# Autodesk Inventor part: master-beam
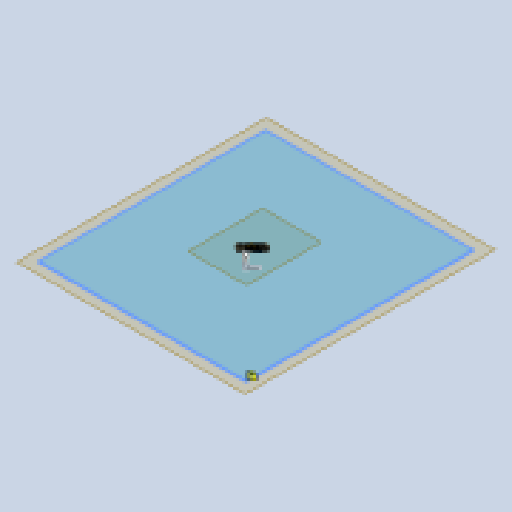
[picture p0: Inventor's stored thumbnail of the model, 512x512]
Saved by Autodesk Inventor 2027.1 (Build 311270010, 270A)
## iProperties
Created: 2026-07
Part Number: master-beam
Material: Generic
Document SubType Name: Modeling
Designer: dunge
Density: 1 g/cm^3
Appearance: Default
Author: dunge
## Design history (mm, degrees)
sketch "master sketch"
  geometry: L1 (0, 0)-(0, 228.6); L2 (0, 228.6)-(-114.3, 228.6); L3 (-114.3, 228.6)-(-114.3, 69.85); L4 (-292.1, 69.85)-(-292.1, 171.45); L5 (-342.9, 69.85)-(-342.9, -35.56); L6 (-342.9, -35.56)-(-241.3, -35.56); L7 (-342.9, -35.56)-(-342.9, 120.808); L8 (-114.3, 69.85)-(-114.3, -6.35); L9 (-342.9, -35.56)-(-342.9, -187.96); 31 further points; 1 other entity
  constraints: 24 point on line, 18 end point, 5 vertical, 3 perpendicular, 1 coincident, 1 midpoint, 10 other
  dimensions: "d0" = 228.6 distance of L1.start L1.end; "d1" = 304.8 distance of L3.end point (-419.1, 69.85); "d2" = 101.6 distance of L4.start L4.end; "d4" = 114.3 distance of L1.end L2.end; "d5" = 76.2 distance of L3.end L8.end; "d6" = 177.8 distance between parallel lines of L3 L4; "d9" = 19.05 distance of point (-190.5, 69.85) point (-171.45, 69.85); "d10" = 19.05 distance of point (-254, 69.85) point (-234.95, 69.85); "d11" = 44.45 distance of point (-234.95, 69.85) point (-190.5, 69.85); "d12" = 57.15 distance from line of L8 point (-171.45, 69.85); "d13" = 127 distance of L1.start point (0, 127); "d14" = 38.1 distance of point (-114.3, 190.5) point (-114.3, 152.4); "d15" = 38.1 distance from line of L2 point (-114.3, 190.5); "d16" = 17.78 distance of point (-342.9, 20.32) point (-342.9, 2.54); "d17" = 17.78 distance of point (-342.9, 20.32) point (-342.9, 38.1); "d18" = 16.51 distance of point (-342.9, -152.4) point (-342.9, -168.91); "d20" = 16.51 distance of point (-342.9, -73.66) point (-342.9, -90.17); "d26" = 152.4 distance of L5.end L9.end; "d27" = 31.75 distance of L5.start point (-342.9, 38.1); "d29" = 35.56 distance of point (-269.24, -35.56) point (-304.8, -35.56); "d40" = 38.1 distance from line of point (-342.9, -73.66) L6; "d42" = 21.59 distance of point (-342.9, -111.76) point (-342.9, -90.17); "d43" = 15.24 distance of point (-342.9, -137.16) point (-342.9, -152.4); "d44" = 25.4 distance of point (-342.9, -137.16) point (-342.9, -111.76); "d45" = 25.4 distance of point (0, 171.45) point (0, 146.05); "d46" = 19.05 distance of point (0, 146.05) point (0, 127); "d47" = 31.75 distance of L3.end point (-114.3, 38.1); "d48" = 31.75 distance of L3.end point (-114.3, 101.6); "d49" = 50.8 distance of point (-114.3, 101.6) point (-114.3, 152.4); "d51" = 31.75 distance of L3.end point (-146.05, 69.85); "d52" = 20.32 distance of point (-292.1, 101.6) point (-292.1, 121.92); "d53" = 20.32 distance of point (-292.1, 142.24) point (-292.1, 121.92); "d54" = 31.75 distance of L4.start point (-292.1, 101.6); "d87" = 101.6 distance of L5.end L6.end; "d88" = 17.78 distance of point (-304.8, -35.56) point (-287.02, -35.56); "d89" = 38.1 distance from line of L7 point (-304.8, -35.56); "d90" = 38.1 distance of point (-342.9, 2.54) L5.end; "d94" = 50.8 distance between parallel lines of L4 L7
workpoint "Work Point1"
workpoint "Work Point2"
workpoint "Work Point3"
workpoint "Work Point4"
workpoint "Work Point5"
workpoint "Work Point6"
workpoint "Work Point7"
workpoint "Work Point8"
workpoint "Work Point9"
workpoint "Work Point10"
workpoint "Work Point11"
workpoint "Work Point12"
workpoint "Work Point13"
workpoint "Work Point14"
workpoint "Work Point15"
workpoint "Work Point16"
workpoint "Work Point17"
workpoint "Work Point18"
workpoint "Work Point19"
workpoint "Work Point20"
workpoint "Work Point21"
workpoint "Work Point22"
workpoint "Work Point23"
workpoint "Work Point24"
workpoint "Work Point25"
sketch "Sketch2"
  geometry: L1 (-114.3, 69.85)-(-419.1, 69.85) reference; L2 (-114.3, 59.69)-(-419.1, 59.69); L3 (-419.1, 59.69)-(-419.1, 69.85); L4 (-114.3, 59.69)-(-114.3, 69.85); 1 further point
  constraints: 6 end point, 2 parallel, 1 vertical
  dimensions: "THICK_BEAM_RADIUS" = 10.16 distance between parallel lines of L1 L2
revolve "Revolution1" sketch "Sketch2" stored, may be unused: angle "d23" = 90 deg
workpoint "Work Point26"
sketch "Sketch3"
  geometry: L1 (-292.1, 69.85)-(-292.1, 171.45) reference; L2 (-302.26, 59.831)-(-302.26, 143.51); L3 (-302.26, 59.831)-(-292.1, 59.831); L4 (-302.26, 143.51)-(-297.307, 171.858); L5 (-297.307, 171.858)-(-297.307, 176.674); L6 (-297.307, 176.674)-(-292.1, 176.674); L7 (-292.1, 176.674)-(-292.1, 171.45); L8 (-292.1, 59.831)-(-292.1, 69.85); 2 further points
  constraints: 14 end point, 2 perpendicular, 2 vertical, 1 collinear, 1 parallel
  dimensions: "d24" = 10.16 distance between parallel lines of L1 L2 (derived); "d56" = 1.27 vertical distance of L2.end point (-292.1, 142.24); "d57" = 5.207 distance between parallel lines of L7 L5; "d58" = 5.22357 distance of L6.end L1.end; "d59" = 4.81531 distance of L4.end L5.end
revolve "LED Beam" sketch "Sketch3" stored, may be unused: angle "d25" = 360 deg
workpoint "Work Point27"
workpoint "Work Point28"
workpoint "Work Point29"
workpoint "Work Point30"
workpoint "Work Point31"
workpoint "Work Point32"
workpoint "Work Point33"
workpoint "Work Point34"
workpoint "Work Point35"
workpoint "Work Point36"
sketch "Sketch4"
  geometry: L1 (-114.3, 228.6)-(-114.3, 69.85) reference; L2 (-104.14, -6.35)-(-104.14, 152.4); L3 (-111.76, 152.4)-(-116.84, 152.4); L4 (-114.3, -6.35)-(-104.14, -6.35); L5 (-111.76, 228.6)-(-114.3, 228.6); L6 (-116.84, 190.5)-(-111.76, 190.5); L7 (-111.76, 190.5)-(-111.76, 228.6); L8 (-104.14, 152.4)-(-114.046, 183.356); L9 (-114.046, 183.356)-(-111.76, 190.5); L10 (-114.3, 69.85)-(-114.3, -6.35) reference; L11 (-113.965, 183.61)-(-114.3, 183.61); L12 (-113.965, 183.102)-(-114.3, 183.102); 4 further points
  constraints: 21 end point, 4 perpendicular, 4 point on line, 2 midpoint, 2 parallel, 2 vertical, 1 horizontal, 1 horizontal alignment, 1 vertical alignment
  dimensions: "d33" = 0.254 distance from line of L1 L8.end; "d60" = 0.254 distance from line of L8.end L11; "d61" = 0.254 distance from line of L8.end L12; "THIN_BEAM_RADIUS" = 2.54 distance between parallel lines of L1 L7; "d63" = 10.16 distance between parallel lines of L1 L2 (derived)
revolve "Revolution3" sketch "Sketch4" stored, may be unused: angle "d34" = 360 deg
workplane "Work Plane1"
sketch "Sketch6"
  geometry: L1 (11597.715, 14740.167)-(-14176.276, 14740.167); L2 (-14176.276, 14740.167)-(-14176.276, -13449.358); L3 (-14176.276, -13449.358)-(11597.715, -13449.358); L4 (11597.715, -13449.358)-(11597.715, 14740.167); 1 further point
  constraints: 8 end point, 2 parallel, 1 horizontal, 1 perpendicular
extrude "Extrusion2" new body sketch "Sketch6" distance "d38" = 25.4; taper "d39" = 0 deg
workpoint "Work Point37"
workpoint "Work Point38"
workpoint "Work Point39"
workpoint "Work Point40"
workpoint "Work Point41"
workpoint "Work Point42"
workpoint "Work Point43"
workpoint "Work Point44"
workplane "Work Plane2"
sketch "Sketch7"
  geometry: L1 (0, 228.6)-(-114.3, 228.6) reference; L2 (0, 0)-(0, 228.6) reference; L3 (0, 145.605)-(0, 146.494) reference; 3 further points
  constraints: 2 end point, 1 vertical, 2 other
workpoint "Work Point45"
workpoint "Work Point46"
workpoint "Work Point47"
workpoint "Work Point48"
workpoint "Work Point49"
sketch "Sketch8"
  geometry: L1 (-116.84, 228.6)-(-111.76, 228.6) reference; 2 further points
  constraints: 1 horizontal alignment, 1 midpoint, 2 other
extrude "Extrusion3" join sketch "Sketch8" distance "d64" = 19.05; taper "d65" = 0 deg
workplane "Work Plane3"
sketch "Sketch9"
  geometry: L1 (2.54, 0)-(-2.54, 0) reference; C1 r 12.7 at (0, 0); 1 further point
  constraints: 1 centre point, 1 midpoint
  dimensions: "d66" = 25.4 diameter of C1
extrude "Extrusion4" cut sketch "Sketch9" distance "d67" = 19.05; taper "d68" = 0 deg
sketch "Sketch10"
  geometry: L1 (0, 228.6)-(-114.3, 228.6) reference; L2 (0, 0)-(0, 228.6) reference; L3 (-114.3, 228.6)-(0, 228.6); L4 (0, 228.6)-(0, 231.14); L5 (0, 231.14)-(-114.3, 231.14); L6 (-114.3, 231.14)-(-114.3, 228.6); L7 (0, 228.6)-(2.54, 228.6); L8 (2.54, 228.6)-(2.54, 0); L9 (2.54, 0)-(0, 0); L10 (0, 0)-(0, 228.6); 4 further points
  constraints: 16 end point, 4 parallel, 2 horizontal, 2 perpendicular
  dimensions: "d69" = 2.54 distance of L8.end L9.end (derived); "d70" = 2.54 distance of L3.end L4.end (derived)
revolve "Revolution4" stored, may be unused: angle "d71" = 90 deg
revolve "Revolution5" stored, may be unused: angle "d72" = 360 deg
workplane "Work Plane4"
sketch "Sketch11"
  geometry: C1 r 10.368 at (-0.227, -0.06); 1 further point
  constraints: 1 centre point
extrude "Extrusion5" cut sketch "Sketch11" distance "d73" = 19.05; taper "d74" = 0 deg
workplane "Work Plane5"
sketch "Sketch12"
  geometry: L1 (-2.54, 0)-(2.54, 0) reference; C1 r 24.504 at (-0.617, 0); 1 further point
  constraints: 1 centre point, 1 point on line
extrude "Extrusion6" cut sketch "Sketch12" distance "d75" = 19.05; taper "d76" = 0 deg
sketch "Sketch13"
  geometry: L1 (-342.9, 54.915)-(-342.9, 84.785) reference; L2 (-357.835, 69.85)-(-327.965, 69.85) reference; L3 (-342.9, 20.411)-(-342.9, -33.65) reference; L4 (-241.554, -25.281)-(-241.554, -46.853) reference; L5 (-352.74, -183.96)-(-333.06, -183.96) reference; L6 (-342.9, -280.735)-(-342.9, -133.286) reference; L7 (-342.9, 69.85)-(-332.74, 59.69); L8 (-332.74, 59.69)-(-332.74, -10.16); L9 (-332.74, -10.16)-(-342.9, -35.56); L10 (-342.9, -35.56)-(-317.5, -45.72); L11 (-342.9, -35.56)-(-353.06, -60.96); L12 (-342.9, 54.915)-(-342.9, 2.54); L13 (-353.06, -60.96)-(-353.06, -168.91); L14 (-353.06, -168.91)-(-346.71, -183.96); L15 (-342.9, -133.286)-(-342.9, -33.65); L16 (-317.5, -45.72)-(-269.24, -45.72); L17 (-269.24, -45.72)-(-239.875, -38.733); L18 (-239.875, -38.733)-(-239.875, -35.56); L19 (-241.241, -35.56)-(-342.9, -35.56); L20 (-241.241, -35.56)-(-239.875, -35.56); L21 (-241.554, -35.56)-(-241.554, -39.132); L22 (-342.9, -35.56)-(-353.06, -60.96); L23 (-353.06, -168.91)-(-346.71, -183.96); L24 (-342.9, -183.96)-(-342.9, -35.56); 9 further points
  constraints: 44 end point, 8 vertical, 6 point on line, 3 collinear, 3 horizontal, 3 perpendicular, 2 midpoint, 1 horizontal alignment, 1 vertical alignment, 8 other
  dimensions: "d78" = 45 deg angle of L1 L7; "d79" = 10.16 distance between parallel lines of L1 L8 (derived); "d80" = 10.16 distance between parallel lines of L15 L13 (derived); "d82" = 3.17252 distance of L17.end L18.end; "d83" = 1.67902 distance from line of L17.end L4; "d84" = 3.81 distance from line of L6 L14.end; "d91" = 10.16 distance between parallel lines of L19 L16 (derived)
revolve "Revolution6" sketch "Sketch13" stored, may be unused: angle "d92" = 360 deg
sketch "Sketch14"
  geometry: L1 (-239.875, -38.733)-(-239.875, -35.56) reference; L2 (-241.241, -35.56)-(-342.9, -35.56) reference; L3 (-241.241, -35.56)-(-239.875, -35.56) reference; L4 (-269.24, -45.72)-(-239.875, -38.733) reference; L5 (-342.9, -35.56)-(-317.5, -45.72) reference; L6 (-317.5, -45.72)-(-269.24, -45.72) reference; 1 further point
revolve "Revolution7" sketch "Sketch14" stored, may be unused: angle "d93" = 360 deg
sketch "Sketch15"
  geometry: L1 (-281.94, 69.85)-(-419.1, 69.85); L2 (-419.1, 69.85)-(-419.1, 80.01); L3 (-419.1, 80.01)-(-281.94, 80.01); L4 (-281.94, 80.01)-(-281.94, 69.85); 2 further points
  constraints: 8 end point, 2 parallel, 1 coincident, 1 horizontal, 1 perpendicular
  dimensions: "d95" = 10.16 distance of L1.end L2.end (derived)
revolve "Revolution8" sketch "Sketch15" stored, may be unused: angle "d96" = 90 deg
workplane "Work Plane6"
sketch "Sketch16"
  geometry: C1 r 22.998 at (0, -0.97); 1 further point
  constraints: 1 centre point
extrude "Extrusion7" cut sketch "Sketch16" distance "d97" = 25.4; taper "d98" = 0 deg
sketch "Sketch17"
  geometry: L1 (-342.9, -133.286)-(-342.9, -33.65) reference; L2 (-342.9, -35.56)-(-353.06, -60.96) reference; L3 (-353.06, -60.96)-(-353.06, -168.91) reference; L4 (-353.06, -168.91)-(-346.71, -183.96) reference; L5 (-342.9, -183.96)-(-342.9, -35.56) reference; L6 (-346.71, -183.96)-(-342.9, -183.96); 1 further point
  constraints: 2 end point, 1 horizontal
revolve "Revolution9" sketch "Sketch17" stored, may be unused: angle "d99" = 90 deg
node "red beam"
node "blue beam"
node "red beam 2"
node "white plane"
node "Reference1"
node "Reference2"
node "green beam"
node "blue beam 2"
node "green 2"
node "green 3"
other parameters: "d37" = -38.1, "d55" = -19.05
